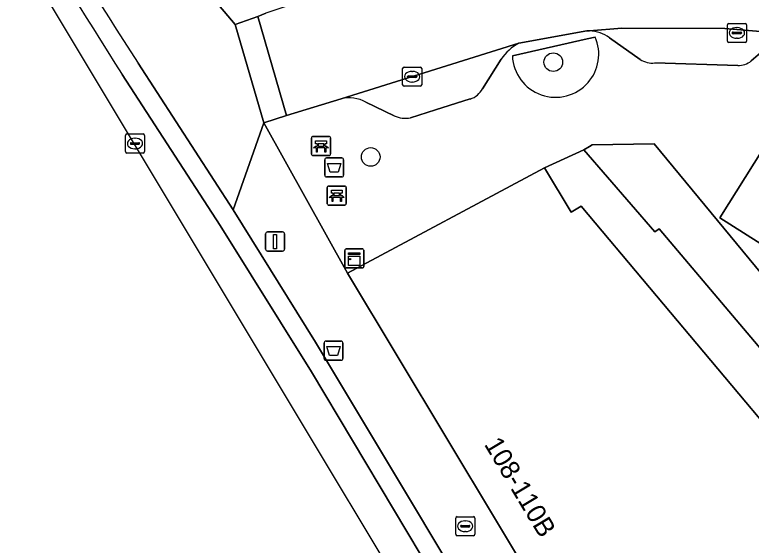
# Model space of a CAD drawing. Extents: x 160856 to 161310, y 384024 to 384878.
# Drawn here: x 161076.43 to 161115.03, y 384389.95 to 384417.77 of the extents above; entities that cross this region are included whole.
import ezdxf

# ---------------------------------------------------------------- set-up
doc = ezdxf.new("R2010")
doc.units = 0
for name, color, linetype in [('IMGEO_Afvalbak', 7, 'Continuous'), ('IMGEO_Bank', 7, 'Continuous'), ('IMGEO_Boom', 7, 'Continuous'), ('IMGEO_Erf', 7, 'Continuous'), ('IMGEO_Fietspad_gesloten', 7, 'Continuous'), ('IMGEO_Fietspad_open', 7, 'Continuous'), ('IMGEO_Groenvoorziening', 7, 'Continuous'), ('IMGEO_Kast', 7, 'Continuous'), ('IMGEO_Kolk', 7, 'Continuous'), ('IMGEO_Lichtmast', 7, 'Continuous'), ('IMGEO_Pand', 7, 'Continuous'), ('IMGEO_Pand_nummerreeks', 7, 'Continuous'), ('IMGEO_Parkeervlak_open', 7, 'Continuous'), ('IMGEO_Rijbaan_lokaal_open', 7, 'Continuous'), ('IMGEO_Rioolput', 7, 'Continuous'), ('IMGEO_Voetpad_open', 7, 'Continuous')]:
    doc.layers.add(name, color=color, linetype=linetype)

msp = doc.modelspace()

# ---------------------------------------------------------------- linework, layer by layer
at = {"layer": 'IMGEO_Afvalbak'}
for p, q in [((161092.675, 384409.364), (161092.675, 384410.164)), ((161092.675, 384410.164), (161092.675, 384409.364)), ((161092.775, 384410.264), (161093.565, 384410.264)), ((161093.565, 384410.264), (161092.775, 384410.264)), ((161093.665, 384410.164), (161093.665, 384409.364)), ((161093.665, 384409.364), (161093.665, 384410.164)), ((161093.565, 384409.264), (161092.775, 384409.264)), ((161092.775, 384409.264), (161093.565, 384409.264)), ((161092.643, 384399.751), (161092.643, 384400.551)), ((161092.643, 384400.551), (161092.643, 384399.751)), ((161092.743, 384400.651), (161093.533, 384400.651)), ((161093.533, 384400.651), (161092.743, 384400.651)), ((161093.633, 384400.551), (161093.633, 384399.751)), ((161093.633, 384399.751), (161093.633, 384400.551)), ((161093.533, 384399.651), (161092.743, 384399.651)), ((161092.743, 384399.651), (161093.533, 384399.651))]:
    msp.add_line(p, q, dxfattribs=at)
for points in [[(161092.818, 384409.978), (161093.522, 384409.978), (161093.373, 384409.508), (161092.967, 384409.508), (161092.818, 384409.978)], [(161092.786, 384400.365), (161093.49, 384400.365), (161093.341, 384399.895), (161092.935, 384399.895), (161092.786, 384400.365)]]:
    msp.add_lwpolyline(points, dxfattribs=at)
for centre, start, end in [((161092.775, 384410.164), 90, 180), ((161092.775, 384410.164), 90, 180), ((161093.565, 384410.164), 0, 90), ((161093.565, 384410.164), 360, 90), ((161092.775, 384409.364), 180, 270), ((161092.775, 384409.364), 180, 270), ((161093.565, 384409.364), 270, 0), ((161093.565, 384409.364), 270, 0), ((161092.743, 384400.551), 90, 180), ((161092.743, 384400.551), 90, 180), ((161093.533, 384400.551), 0, 90), ((161093.533, 384400.551), 360, 90), ((161092.743, 384399.751), 180, 270), ((161092.743, 384399.751), 180, 270), ((161093.533, 384399.751), 270, 0), ((161093.533, 384399.751), 270, 0)]:
    msp.add_arc(centre, 0.1, start, end, dxfattribs=at)
at = {"layer": 'IMGEO_Bank'}
for p, q in [((161091.984, 384410.461), (161091.984, 384411.302)), ((161091.984, 384411.302), (161091.984, 384410.461)), ((161092.059, 384411.386), (161092.9, 384411.386)), ((161092.9, 384411.386), (161092.059, 384411.386)), ((161092.984, 384411.311), (161092.984, 384410.47)), ((161092.984, 384410.47), (161092.984, 384411.311)), ((161092.293, 384410.892), (161092.293, 384410.998)), ((161092.337, 384410.998), (161092.337, 384410.892)), ((161092.625, 384411.004), (161092.343, 384411.004)), ((161092.343, 384410.886), (161092.625, 384410.886)), ((161092.631, 384410.892), (161092.631, 384410.998)), ((161092.675, 384410.998), (161092.675, 384410.892)), ((161092.681, 384410.784), (161092.288, 384410.784)), ((161092.909, 384410.386), (161092.068, 384410.386)), ((161092.068, 384410.386), (161092.909, 384410.386)), ((161092.807, 384407.863), (161092.807, 384408.704)), ((161092.807, 384408.704), (161092.807, 384407.863)), ((161092.882, 384408.788), (161093.723, 384408.788)), ((161093.723, 384408.788), (161092.882, 384408.788)), ((161093.807, 384408.713), (161093.807, 384407.872)), ((161093.807, 384407.872), (161093.807, 384408.713)), ((161093.504, 384408.186), (161093.111, 384408.186)), ((161093.116, 384408.294), (161093.116, 384408.4)), ((161093.16, 384408.4), (161093.16, 384408.294)), ((161093.448, 384408.406), (161093.166, 384408.406)), ((161093.166, 384408.288), (161093.448, 384408.288)), ((161093.454, 384408.294), (161093.454, 384408.4)), ((161093.498, 384408.4), (161093.498, 384408.294)), ((161093.732, 384407.788), (161092.891, 384407.788)), ((161092.891, 384407.788), (161093.732, 384407.788))]:
    msp.add_line(p, q, dxfattribs=at)
for points in [[(161092.231, 384410.784), (161092.089, 384410.784), (161092.201, 384410.886), (161092.287, 384410.886)], [(161092.287, 384411.004), (161092.201, 384411.004), (161092.201, 384411.165), (161092.764, 384411.165), (161092.764, 384411.004), (161092.681, 384411.004)], [(161092.681, 384410.886), (161092.764, 384410.886), (161092.876, 384410.784), (161092.737, 384410.784)], [(161092.281, 384410.777), (161092.281, 384410.57), (161092.238, 384410.57), (161092.238, 384410.777)], [(161092.731, 384410.777), (161092.731, 384410.57), (161092.687, 384410.57), (161092.687, 384410.777)], [(161093.11, 384408.406), (161093.024, 384408.406), (161093.024, 384408.567), (161093.587, 384408.567), (161093.587, 384408.406), (161093.504, 384408.406)], [(161093.054, 384408.186), (161092.912, 384408.186), (161093.024, 384408.288), (161093.11, 384408.288)], [(161093.104, 384408.179), (161093.104, 384407.972), (161093.061, 384407.972), (161093.061, 384408.179)], [(161093.504, 384408.288), (161093.587, 384408.288), (161093.699, 384408.186), (161093.56, 384408.186)], [(161093.554, 384408.179), (161093.554, 384407.972), (161093.51, 384407.972), (161093.51, 384408.179)]]:
    msp.add_lwpolyline(points, dxfattribs=at)
for centre, radius, start, end in [((161092.062, 384411.308), 0.0779, 92.4484, 184.2845), ((161092.062, 384411.308), 0.0779, 92.4484, 184.2845), ((161092.906, 384411.308), 0.0779, 2.4484, 94.2845), ((161092.906, 384411.308), 0.0779, 2.4484, 94.2845), ((161092.286, 384410.997), 0.00671, 2.8957, 87.1043), ((161092.286, 384410.893), 0.00671, 272.8957, 357.1043), ((161092.343, 384410.997), 0.00671, 92.8957, 177.1043), ((161092.343, 384410.893), 0.00671, 182.8957, 267.1043), ((161092.625, 384410.997), 0.00671, 2.8957, 87.1043), ((161092.625, 384410.893), 0.00671, 272.8957, 357.1043), ((161092.682, 384410.997), 0.00671, 92.8957, 177.1043), ((161092.682, 384410.893), 0.00671, 182.8957, 267.1043), ((161092.062, 384410.464), 0.0779, 182.4484, 274.2845), ((161092.062, 384410.464), 0.0779, 182.4484, 274.2845), ((161092.231, 384410.777), 0.00671, 2.8957, 87.1043), ((161092.288, 384410.777), 0.00671, 92.8957, 177.1043), ((161092.68, 384410.777), 0.00671, 2.8957, 87.1043), ((161092.737, 384410.777), 0.00671, 92.8957, 177.1043), ((161092.906, 384410.464), 0.0779, 272.4484, 4.2845), ((161092.906, 384410.464), 0.0779, 272.4484, 4.2845), ((161092.885, 384408.71), 0.0779, 92.4484, 184.2845), ((161092.885, 384408.71), 0.0779, 92.4484, 184.2845), ((161093.729, 384408.71), 0.0779, 2.4484, 94.2845), ((161093.729, 384408.71), 0.0779, 2.4484, 94.2845), ((161093.054, 384408.179), 0.00671, 2.8957, 87.1043), ((161093.111, 384408.179), 0.00671, 92.8957, 177.1043), ((161093.109, 384408.399), 0.00671, 2.8957, 87.1043), ((161093.109, 384408.295), 0.00671, 272.8957, 357.1043), ((161093.166, 384408.399), 0.00671, 92.8957, 177.1043), ((161093.166, 384408.295), 0.00671, 182.8957, 267.1043), ((161093.448, 384408.399), 0.00671, 2.8957, 87.1043), ((161093.448, 384408.295), 0.00671, 272.8957, 357.1043), ((161093.505, 384408.399), 0.00671, 92.8957, 177.1043), ((161093.505, 384408.295), 0.00671, 182.8957, 267.1043), ((161093.503, 384408.179), 0.00671, 2.8957, 87.1043), ((161093.56, 384408.179), 0.00671, 92.8957, 177.1043), ((161092.885, 384407.866), 0.0779, 182.4484, 274.2845), ((161092.885, 384407.866), 0.0779, 182.4484, 274.2845), ((161093.729, 384407.866), 0.0779, 272.4484, 4.2845), ((161093.729, 384407.866), 0.0779, 272.4484, 4.2845)]:
    msp.add_arc(centre, radius, start, end, dxfattribs=at)
at = {"layer": 'IMGEO_Boom'}
for centre in [(161104.654, 384415.283), (161095.087, 384410.314)]:
    msp.add_circle(centre, 0.489, dxfattribs=at)
at = {"layer": 'IMGEO_Erf'}
msp.add_lwpolyline([(161104.191, 384409.745), (161105.586, 384407.418), (161106.109, 384407.732), (161116.852, 384394.93), (161119.914, 384391.281), (161122.034, 384392.553), (161110.199, 384406.544), (161109.984, 384406.381), (161106.258, 384410.694)], close=True, dxfattribs=at)
at = {"layer": 'IMGEO_Fietspad_gesloten'}
for points in [[(161070.245, 384433.902), (161065.64, 384441.67), (161064.671, 384443.305), (161063.662, 384442.699), (161082.105, 384411.951), (161105.789, 384372.466), (161110.674, 384361.063)], [(161110.674, 384361.063), (161112.849, 384362.057), (161112.857, 384362.06), (161102.724, 384381.028), (161091.987, 384399.041), (161087.193, 384406.722), (161082.056, 384414.64)]]:
    msp.add_lwpolyline(points, dxfattribs=at)
msp.add_arc((161797.9, 384866.831), 846.705, 210.751128, 212.280142, dxfattribs=at)
at = {"layer": 'IMGEO_Fietspad_open'}
for points in [[(161103.576, 384381.595), (161092.193, 384400.605), (161087.871, 384407.534), (161082.898, 384415.232)], [(161082.056, 384414.64), (161087.193, 384406.722), (161091.987, 384399.041), (161102.724, 384381.028), (161112.857, 384362.06), (161113.016, 384362.133), (161113.775, 384362.52)]]:
    msp.add_lwpolyline(points, dxfattribs=at)
for centre, radius, start, end in [((161497.045, 384682.442), 492.868, 210.20357, 212.83035), ((161797.9, 384866.831), 846.705, 210.751128, 212.280142)]:
    msp.add_arc(centre, radius, start, end, dxfattribs=at)
at = {"layer": 'IMGEO_Groenvoorziening'}
msp.add_lwpolyline([(161106.852, 384416.604), (161106.426, 384416.506), (161102.51, 384415.611)], dxfattribs=at)
for centre, radius, start, end in [((161104.775, 384415.707), 2.262, 318.7466, 23.3648), ((161104.773, 384415.707), 2.265, 182.4364, 318.7803)]:
    msp.add_arc(centre, radius, start, end, dxfattribs=at)
at = {"layer": 'IMGEO_Kast'}
for p, q in [((161093.723, 384404.567), (161093.723, 384405.408)), ((161093.723, 384405.408), (161093.723, 384404.567)), ((161093.798, 384405.492), (161094.639, 384405.492)), ((161094.639, 384405.492), (161093.798, 384405.492)), ((161094.723, 384405.417), (161094.723, 384404.576)), ((161094.723, 384404.576), (161094.723, 384405.417)), ((161094.648, 384404.492), (161093.807, 384404.492)), ((161093.807, 384404.492), (161094.648, 384404.492))]:
    msp.add_line(p, q, dxfattribs=at)
for points in [[(161093.918, 384405.282), (161094.518, 384405.282), (161094.518, 384405.197), (161093.918, 384405.197), (161093.918, 384405.282)], [(161093.918, 384405.107), (161094.518, 384405.107), (161094.518, 384404.618), (161093.918, 384404.618), (161093.918, 384405.107)]]:
    msp.add_lwpolyline(points, dxfattribs=at)
msp.add_circle((161094.002, 384404.956), 0.0377, dxfattribs=at)
for centre, start, end in [((161093.801, 384405.414), 92.4484, 184.2845), ((161093.801, 384405.414), 92.4484, 184.2845), ((161094.645, 384405.414), 2.4484, 94.2845), ((161094.645, 384405.414), 2.4484, 94.2845), ((161093.801, 384404.57), 182.4484, 274.2845), ((161093.801, 384404.57), 182.4484, 274.2845), ((161094.645, 384404.57), 272.4484, 4.2845), ((161094.645, 384404.57), 272.4484, 4.2845)]:
    msp.add_arc(centre, 0.0779, start, end, dxfattribs=at)
at = {"layer": 'IMGEO_Kolk'}
for p, q in [((161113.779, 384416.391), (161113.779, 384417.243)), ((161113.854, 384417.317), (161114.706, 384417.317)), ((161114.267, 384417.097), (161114.292, 384417.097)), ((161114.78, 384417.243), (161114.78, 384416.391)), ((161114.038, 384416.811), (161114.038, 384416.823)), ((161114.476, 384416.774), (161114.078, 384416.774)), ((161114.081, 384416.86), (161114.479, 384416.86)), ((161114.522, 384416.823), (161114.522, 384416.811)), ((161114.706, 384416.317), (161113.854, 384416.317)), ((161114.29, 384416.537), (161114.265, 384416.537)), ((161096.759, 384414.097), (161096.759, 384414.949)), ((161096.834, 384415.023), (161097.686, 384415.023)), ((161097.247, 384414.803), (161097.272, 384414.803)), ((161097.76, 384414.949), (161097.76, 384414.097)), ((161097.018, 384414.517), (161097.018, 384414.529)), ((161097.456, 384414.48), (161097.058, 384414.48)), ((161097.061, 384414.566), (161097.459, 384414.566)), ((161097.502, 384414.529), (161097.502, 384414.517)), ((161097.686, 384414.023), (161096.834, 384414.023)), ((161097.27, 384414.243), (161097.245, 384414.243)), ((161099.539, 384390.521), (161099.539, 384391.373)), ((161099.614, 384391.447), (161100.466, 384391.447)), ((161100.027, 384391.227), (161100.052, 384391.227)), ((161100.54, 384391.373), (161100.54, 384390.521)), ((161099.798, 384390.941), (161099.798, 384390.953)), ((161100.236, 384390.904), (161099.838, 384390.904)), ((161099.841, 384390.99), (161100.239, 384390.99)), ((161100.282, 384390.953), (161100.282, 384390.941)), ((161100.466, 384390.447), (161099.614, 384390.447)), ((161100.05, 384390.667), (161100.025, 384390.667))]:
    msp.add_line(p, q, dxfattribs=at)
for points in [[(161113.779, 384416.391), (161113.779, 384417.243)], [(161113.854, 384417.317), (161114.706, 384417.317)], [(161114.78, 384417.243), (161114.78, 384416.391)], [(161114.706, 384416.317), (161113.854, 384416.317)], [(161096.759, 384414.097), (161096.759, 384414.949)], [(161096.834, 384415.023), (161097.686, 384415.023)], [(161097.76, 384414.949), (161097.76, 384414.097)], [(161097.686, 384414.023), (161096.834, 384414.023)], [(161099.539, 384390.521), (161099.539, 384391.373)], [(161099.614, 384391.447), (161100.466, 384391.447)], [(161100.54, 384391.373), (161100.54, 384390.521)], [(161100.466, 384390.447), (161099.614, 384390.447)]]:
    msp.add_lwpolyline(points, dxfattribs=at)
for centre, radius, start, end in [((161113.856, 384417.241), 0.0765, 91.552, 178.448), ((161113.856, 384417.241), 0.0765, 91.552, 178.448), ((161114.704, 384417.241), 0.0765, 1.552, 88.448), ((161114.704, 384417.241), 0.0765, 1.552, 88.448), ((161114.078, 384416.82), 0.0403, 85.8775, 175.7526), ((161114.075, 384416.81), 0.0366, 178.938, 274.7102), ((161114.479, 384416.817), 0.043, 264.8664, 352.4533), ((161114.483, 384416.822), 0.0386, 1.7309, 96.639), ((161113.856, 384416.393), 0.0765, 181.552, 268.448), ((161113.856, 384416.393), 0.0765, 181.552, 268.448), ((161114.704, 384416.393), 0.0765, 271.552, 358.448), ((161114.704, 384416.393), 0.0765, 271.552, 358.448), ((161096.836, 384414.947), 0.0765, 91.552, 178.448), ((161096.836, 384414.947), 0.0765, 91.552, 178.448), ((161097.684, 384414.947), 0.0765, 1.552, 88.448), ((161097.684, 384414.947), 0.0765, 1.552, 88.448), ((161097.058, 384414.526), 0.0403, 85.8775, 175.7526), ((161097.055, 384414.516), 0.0366, 178.938, 274.7102), ((161097.459, 384414.523), 0.043, 264.8664, 352.4533), ((161097.463, 384414.528), 0.0386, 1.7309, 96.639), ((161096.836, 384414.099), 0.0765, 181.552, 268.448), ((161096.836, 384414.099), 0.0765, 181.552, 268.448), ((161097.684, 384414.099), 0.0765, 271.552, 358.448), ((161097.684, 384414.099), 0.0765, 271.552, 358.448), ((161099.616, 384391.371), 0.0765, 91.552, 178.448), ((161099.616, 384391.371), 0.0765, 91.552, 178.448), ((161100.464, 384391.371), 0.0765, 1.552, 88.448), ((161100.464, 384391.371), 0.0765, 1.552, 88.448), ((161099.838, 384390.95), 0.0403, 85.8775, 175.7526), ((161099.835, 384390.94), 0.0366, 178.938, 274.7102), ((161100.239, 384390.947), 0.043, 264.8664, 352.4533), ((161100.243, 384390.952), 0.0386, 1.7309, 96.639), ((161099.616, 384390.523), 0.0765, 181.552, 268.448), ((161099.616, 384390.523), 0.0765, 181.552, 268.448), ((161100.464, 384390.523), 0.0765, 271.552, 358.448), ((161100.464, 384390.523), 0.0765, 271.552, 358.448)]:
    msp.add_arc(centre, radius, start, end, dxfattribs=at)
for centre, major_axis, ratio, start_param, end_param in [((161114.266, 384416.817), (-0.387, 0.002), 0.722429, 4.712389, 7.853982), ((161114.291, 384416.817), (-0.39, 0.002), 0.717154, 1.570796, 4.712389), ((161097.246, 384414.523), (-0.387, 0.002), 0.722429, 4.712389, 7.853982), ((161097.271, 384414.523), (-0.39, 0.002), 0.717154, 1.570796, 4.712389), ((161100.026, 384390.947), (-0.387, 0.002), 0.722429, 4.712389, 7.853982), ((161100.051, 384390.947), (-0.39, 0.002), 0.717154, 1.570796, 4.712389)]:
    msp.add_ellipse(centre, major_axis=major_axis, ratio=ratio, start_param=start_param, end_param=end_param, dxfattribs=at)
at = {"layer": 'IMGEO_Lichtmast'}
for p, q in [((161089.579, 384405.478), (161089.579, 384406.278)), ((161089.579, 384406.278), (161089.579, 384405.478)), ((161089.679, 384406.378), (161090.469, 384406.378)), ((161090.469, 384406.378), (161089.679, 384406.378)), ((161090.569, 384406.278), (161090.569, 384405.478)), ((161090.569, 384405.478), (161090.569, 384406.278)), ((161090.469, 384405.378), (161089.679, 384405.378)), ((161089.679, 384405.378), (161090.469, 384405.378))]:
    msp.add_line(p, q, dxfattribs=at)
msp.add_lwpolyline([(161089.999, 384406.253), (161090.149, 384406.253), (161090.149, 384405.503), (161089.999, 384405.503), (161089.999, 384406.253)], dxfattribs=at)
for centre, start, end in [((161089.679, 384406.278), 90, 180), ((161089.679, 384406.278), 90, 180), ((161090.469, 384406.278), 0, 90), ((161090.469, 384406.278), 360, 90), ((161089.679, 384405.478), 180, 270), ((161089.679, 384405.478), 180, 270), ((161090.469, 384405.478), 270, 0), ((161090.469, 384405.478), 270, 0)]:
    msp.add_arc(centre, 0.1, start, end, dxfattribs=at)
at = {"layer": 'IMGEO_Pand'}
msp.add_lwpolyline([(161106.109, 384407.732), (161105.586, 384407.418), (161104.191, 384409.745), (161093.874, 384404.221), (161104.277, 384386.876), (161108.604, 384379.661), (161115.334, 384382.426), (161127.77, 384389.008), (161127.256, 384389.683), (161124.121, 384393.803), (161124.016, 384393.931), (161120.674, 384397.984), (161116.578, 384402.952), (161109.935, 384411.01), (161106.695, 384410.956), (161106.55, 384410.869), (161106.258, 384410.694), (161109.984, 384406.381), (161110.199, 384406.544), (161122.034, 384392.553), (161119.914, 384391.281), (161116.852, 384394.93)], close=True, dxfattribs=at)
at = {"layer": 'IMGEO_Parkeervlak_open'}
for points in [[(161117.381, 384416.743), (161113.654, 384417.056), (161108.247, 384417.06), (161106.556, 384416.929)], [(161102.844, 384416.277), (161093.535, 384413.354)], [(161107.605, 384416.563), (161109.215, 384415.432)], [(161115.031, 384415.346), (161116.132, 384416.3)], [(161100.943, 384413.893), (161101.926, 384415.442)], [(161109.973, 384415.241), (161114.326, 384415.112)], [(161094.838, 384413.19), (161096.323, 384412.473)], [(161097.171, 384412.367), (161098.478, 384412.778), (161100.306, 384413.353)], [(161116.037, 384411.344), (161113.39, 384407.121), (161116.779, 384404.964)]]:
    msp.add_lwpolyline(points, dxfattribs=at)
for centre, radius, start, end in [((161106.462, 384414.974), 1.957, 54.2775, 87.2544), ((161104.094, 384413.981), 2.614, 118.5594, 146.0191), ((161109.842, 384416.319), 1.086, 234.7658, 276.9484), ((161114.344, 384416.237), 1.125, 269.0812, 307.6424), ((161099.944, 384414.425), 1.132, 288.6406, 331.9369), ((161093.977, 384411.608), 1.801, 61.4432, 104.2093), ((161096.916, 384413.771), 1.427, 245.4477, 280.3023)]:
    msp.add_arc(centre, radius, start, end, dxfattribs=at)
at = {"layer": 'IMGEO_Rijbaan_lokaal_open'}
msp.add_lwpolyline([(161101.876, 384421.785), (161098.531, 384420.85), (161089.588, 384417.86), (161089.167, 384417.686), (161090.67, 384412.482), (161093.535, 384413.354), (161102.844, 384416.277), (161106.417, 384416.93), (161106.556, 384416.929), (161108.247, 384417.06), (161113.654, 384417.056), (161117.381, 384416.743), (161121.414, 384416.288)], dxfattribs=at)
at = {"layer": 'IMGEO_Rioolput'}
for p, q in [((161082.232, 384410.592), (161082.232, 384411.444)), ((161082.307, 384411.518), (161083.159, 384411.518)), ((161082.72, 384411.298), (161082.745, 384411.298)), ((161083.233, 384411.444), (161083.233, 384410.592)), ((161082.491, 384411.012), (161082.491, 384411.024)), ((161082.929, 384410.975), (161082.531, 384410.975)), ((161082.534, 384411.061), (161082.932, 384411.061)), ((161082.975, 384411.024), (161082.975, 384411.012)), ((161083.159, 384410.518), (161082.307, 384410.518)), ((161082.743, 384410.738), (161082.718, 384410.738))]:
    msp.add_line(p, q, dxfattribs=at)
for points in [[(161082.232, 384410.592), (161082.232, 384411.444)], [(161082.307, 384411.518), (161083.159, 384411.518)], [(161083.233, 384411.444), (161083.233, 384410.592)], [(161083.159, 384410.518), (161082.307, 384410.518)]]:
    msp.add_lwpolyline(points, dxfattribs=at)
for centre, radius, start, end in [((161082.309, 384411.442), 0.0765, 91.552, 178.448), ((161082.309, 384411.442), 0.0765, 91.552, 178.448), ((161083.157, 384411.442), 0.0765, 1.552, 88.448), ((161083.157, 384411.442), 0.0765, 1.552, 88.448), ((161082.531, 384411.021), 0.0403, 85.8775, 175.7526), ((161082.528, 384411.011), 0.0366, 178.938, 274.7102), ((161082.932, 384411.018), 0.043, 264.8664, 352.4533), ((161082.936, 384411.023), 0.0386, 1.7309, 96.639), ((161082.309, 384410.594), 0.0765, 181.552, 268.448), ((161082.309, 384410.594), 0.0765, 181.552, 268.448), ((161083.157, 384410.594), 0.0765, 271.552, 358.448), ((161083.157, 384410.594), 0.0765, 271.552, 358.448)]:
    msp.add_arc(centre, radius, start, end, dxfattribs=at)
for centre, major_axis, ratio, start_param, end_param in [((161082.719, 384411.018), (-0.387, 0.002), 0.722429, 4.712389, 7.853982), ((161082.744, 384411.018), (-0.39, 0.002), 0.717154, 1.570796, 4.712389)]:
    msp.add_ellipse(centre, major_axis=major_axis, ratio=ratio, start_param=start_param, end_param=end_param, dxfattribs=at)
at = {"layer": 'IMGEO_Voetpad_open'}
for points in [[(161082.898, 384415.232), (161087.871, 384407.534), (161089.488, 384412.11), (161087.978, 384417.265), (161083.529, 384422.548), (161081.445, 384423.321), (161077.145, 384431.612), (161077.552, 384431.965), (161074.052, 384437.883), (161067.054, 384449.718), (161059.97, 384461.697), (161056.563, 384467.459), (161053.697, 384472.306), (161050.789, 384477.224), (161047.368, 384483.008), (161044.336, 384488.136), (161040.804, 384494.109), (161036.766, 384500)], [(161101.502, 384423.64), (161102.76, 384423.992), (161102.539, 384425.039), (161102.043, 384427.734), (161090.636, 384424.238), (161089.882, 384425.764), (161083.529, 384422.548), (161087.978, 384417.265), (161089.167, 384417.686), (161089.588, 384417.86)], [(161102.51, 384415.611), (161106.426, 384416.506), (161106.852, 384416.604)], [(161106.556, 384416.929), (161106.417, 384416.93), (161102.844, 384416.277)], [(161109.215, 384415.432), (161107.605, 384416.563)], [(161116.132, 384416.3), (161115.031, 384415.346)], [(161101.926, 384415.442), (161100.943, 384413.893)], [(161114.326, 384415.112), (161109.973, 384415.241)], [(161093.535, 384413.354), (161090.67, 384412.482), (161089.488, 384412.11), (161093.874, 384404.221), (161104.191, 384409.745), (161106.258, 384410.694), (161106.55, 384410.869), (161106.695, 384410.956), (161109.935, 384411.01), (161116.578, 384402.952)], [(161096.323, 384412.473), (161094.838, 384413.19)], [(161100.306, 384413.353), (161098.478, 384412.778), (161097.171, 384412.367)], [(161104.277, 384386.876), (161093.874, 384404.221), (161089.488, 384412.11), (161087.871, 384407.534), (161092.193, 384400.605), (161103.576, 384381.595)], [(161116.779, 384404.964), (161113.39, 384407.121), (161116.037, 384411.344)]]:
    msp.add_lwpolyline(points, dxfattribs=at)
msp.add_lwpolyline([(161089.167, 384417.686), (161087.978, 384417.265), (161089.488, 384412.11), (161090.67, 384412.482)], close=True, dxfattribs=at)
for centre, radius, start, end in [((161497.045, 384682.442), 492.868, 210.20357, 212.83035), ((161104.775, 384415.707), 2.262, 318.7466, 23.3648), ((161106.462, 384414.974), 1.957, 54.2775, 87.2544), ((161104.094, 384413.981), 2.614, 118.5594, 146.0191), ((161104.773, 384415.707), 2.265, 182.4364, 318.7803), ((161109.842, 384416.319), 1.086, 234.7658, 276.9484), ((161114.344, 384416.237), 1.125, 269.0812, 307.6424), ((161099.944, 384414.425), 1.132, 288.6406, 331.9369), ((161093.977, 384411.608), 1.801, 61.4432, 104.2093), ((161096.916, 384413.771), 1.427, 245.4477, 280.3023)]:
    msp.add_arc(centre, radius, start, end, dxfattribs=at)

# ---------------------------------------------------------------- texts
at = {"layer": 'IMGEO_Pand_nummerreeks'}
msp.add_text('108-110B', height=1, rotation=300.954, dxfattribs=at).set_placement((161101.007, 384395.244))

doc.saveas('drawing.dxf')
